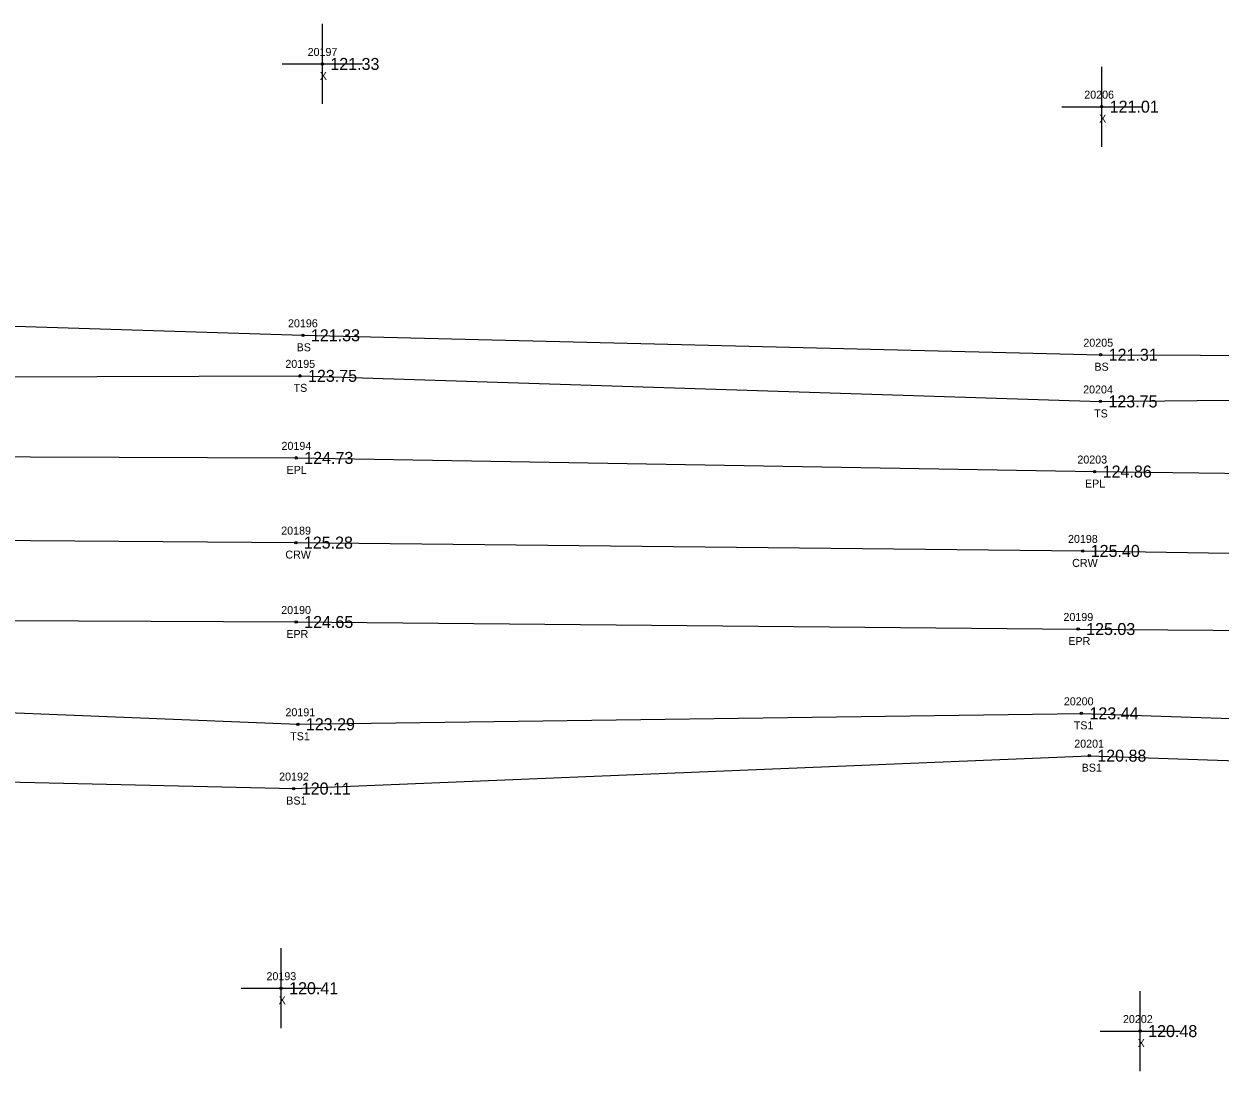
# Model space of a CAD drawing. Extents: x 2375812 to 2377225, y 1024470 to 1025135.
# Drawn here: x 2376931.3 to 2377080.8, y 1024855.9 to 1024986.7 of the extents above; entities that cross this region are included whole.
import ezdxf

# ---------------------------------------------------------------- set-up
doc = ezdxf.new("R2010")
doc.units = 0
for name, color, linetype in [('RD_DTM_BkLn1', 7, 'Continuous'), ('RD_DTM_BkLn2', 7, 'Continuous'), ('RD_DTM_BkLn_txCode', 7, 'Continuous'), ('RD_EX_Misc', 7, 'Continuous'), ('RD_EX_Misc_txCode', 7, 'Continuous'), ('RD_EX_Road', 7, 'Continuous'), ('RD_EX_Road_txCode', 7, 'Continuous'), ('RD_EX_TX_Misc_ELEV', 7, 'Continuous'), ('RD_EX_TX_Road_ELEV', 7, 'Continuous'), ('RD_HC_Survey_ELEV', 7, 'Continuous'), ('RD_HC_Survey_txCode', 7, 'Continuous'), ('RD_SMD_Locator', 7, 'Continuous')]:
    doc.layers.add(name, color=color, linetype=linetype)

msp = doc.modelspace()

# ---------------------------------------------------------------- linework, layer by layer
at = {"layer": 'RD_DTM_BkLn1'}
msp.add_lwpolyline([(2376561.75, 1024926.35), (2376659.86, 1024925.07), (2376762.41, 1024923.95), (2376865.76, 1024922.65), (2376965.3, 1024921.9), (2377063.64, 1024920.86), (2377113.34, 1024920.1), (2377166.94, 1024920.12), (2377217.3, 1024921.22)], dxfattribs=at)
at = {"layer": 'RD_DTM_BkLn2'}
for points in [[(2376538.09, 1024944), (2376550.49, 1024951.37), (2376563.43, 1024953.34), (2376659.84, 1024952.77), (2376765.68, 1024950.71), (2376864.8, 1024951), (2376966.18, 1024947.81), (2377065.88, 1024945.38), (2377115.79, 1024945.18), (2377168.04, 1024944.37), (2377216.91, 1024944.34)], [(2376561.81, 1024938.95), (2376565.65, 1024944.33), (2376658.56, 1024947.18), (2376764.14, 1024946.5), (2376864.38, 1024942.41), (2376965.82, 1024942.74), (2377065.85, 1024939.54), (2377114.14, 1024940.04), (2377167.94, 1024941.05), (2377217.02, 1024940.65)], [(2376561.53, 1024913.62), (2376561.38, 1024909.35), (2376658.21, 1024899.77), (2376672.96, 1024897.91), (2376688.03, 1024903.17), (2376760.99, 1024901.04), (2376828.16, 1024902.22), (2376853.81, 1024902.74), (2376860.1, 1024898.86), (2376865.34, 1024899.92), (2376875.73, 1024904.61), (2376896.78, 1024904.73), (2376899.24, 1024901.87), (2376965.55, 1024899.2), (2377063.48, 1024900.56), (2377114.6, 1024898.84), (2377167.13, 1024900.76), (2377217.62, 1024901.12)], [(2376543.21, 1024910.85), (2376558.6, 1024896.28), (2376588.49, 1024894.01), (2376656.25, 1024894.1), (2376679.22, 1024888.45), (2376688.36, 1024892.22), (2376760.25, 1024888.88), (2376862.95, 1024889.28), (2376867.73, 1024890.58), (2376879.38, 1024883.12), (2376893.75, 1024882.89), (2376900.24, 1024892.67), (2376965.04, 1024891.16), (2377064.46, 1024895.27), (2377115.01, 1024893.54), (2377167.33, 1024895.41), (2377217.32, 1024894.83)]]:
    msp.add_lwpolyline(points, dxfattribs=at)
at = {"layer": 'RD_EX_Misc'}
for p, q in [((2376968.61, 1024976.72), (2376968.61, 1024986.72)), ((2376963.61, 1024981.72), (2376973.61, 1024981.72)), ((2377066.01, 1024971.38), (2377066.01, 1024981.38)), ((2377061.01, 1024976.38), (2377071.01, 1024976.38)), ((2376963.46, 1024861.21), (2376963.46, 1024871.21)), ((2376958.46, 1024866.21), (2376968.46, 1024866.21)), ((2377070.82, 1024855.85), (2377070.82, 1024865.85)), ((2377065.82, 1024860.85), (2377075.82, 1024860.85))]:
    msp.add_line(p, q, dxfattribs=at)
at = {"layer": 'RD_EX_Road'}
for points in [[(2376561.85, 1024938.22), (2376659.62, 1024935.3), (2376763.51, 1024933.89), (2376865.73, 1024932.88), (2376965.35, 1024932.49), (2377065.13, 1024930.78), (2377114.03, 1024930.18), (2377167.22, 1024930.19), (2377217.07, 1024931.12)], [(2376561.38, 1024915.36), (2376658.71, 1024915.48), (2376761.9, 1024913.76), (2376865.54, 1024912.46), (2376965.34, 1024911.98), (2377063.07, 1024911.1), (2377113.55, 1024910.69), (2377167.38, 1024909.96), (2377217.4, 1024910.82)]]:
    msp.add_lwpolyline(points, dxfattribs=at)
at = {"layer": 'RD_SMD_Locator'}
for centre in [(2376968.61, 1024981.72), (2377066.01, 1024976.38), (2376966.18, 1024947.81), (2377065.88, 1024945.38), (2376965.82, 1024942.74), (2377065.85, 1024939.54), (2376965.35, 1024932.49), (2377065.13, 1024930.78), (2376965.3, 1024921.9), (2377063.64, 1024920.86), (2376965.34, 1024911.98), (2377063.07, 1024911.1), (2377063.48, 1024900.56), (2376965.55, 1024899.2), (2377064.46, 1024895.27), (2376965.04, 1024891.16), (2376963.46, 1024866.21), (2377070.82, 1024860.85)]:
    msp.add_circle(centre, 0.15, dxfattribs=at)

# ---------------------------------------------------------------- texts
at = {"layer": 'RD_DTM_BkLn_txCode'}
for s, p in [('20196', (2376964.32, 1024948.81)), ('20205', (2377063.72, 1024946.38)), ('BS', (2376965.4, 1024945.81)), ('20195', (2376963.99, 1024943.74)), ('BS', (2377065.1, 1024943.38)), ('TS', (2376965.02, 1024940.74)), ('20204', (2377063.69, 1024940.54)), ('TS', (2377065.06, 1024937.54)), ('20200', (2377061.28, 1024901.56)), ('20191', (2376964, 1024900.2)), ('TS1', (2377062.52, 1024898.56)), ('TS1', (2376964.59, 1024897.2)), ('20201', (2377062.58, 1024896.27)), ('20192', (2376963.21, 1024892.16)), ('BS1', (2377063.51, 1024893.27)), ('BS1', (2376964.1, 1024889.16))]:
    msp.add_text(s, height=1, dxfattribs=at).set_placement(p)
at = {"layer": 'RD_EX_Misc_txCode'}
for s, p in [('20197', (2376966.77, 1024982.72)), ('X', (2376968.29, 1024979.72)), ('20206', (2377063.83, 1024977.38)), ('X', (2377065.7, 1024974.38)), ('20193', (2376961.63, 1024867.21)), ('X', (2376963.15, 1024864.21)), ('20202', (2377068.67, 1024861.85)), ('X', (2377070.51, 1024858.85))]:
    msp.add_text(s, height=1, dxfattribs=at).set_placement(p)
at = {"layer": 'RD_EX_Road_txCode'}
for s, p in [('20194', (2376963.51, 1024933.49)), ('20203', (2377062.97, 1024931.78)), ('EPL', (2376964.14, 1024930.49)), ('EPL', (2377063.92, 1024928.78)), ('20190', (2376963.47, 1024912.98)), ('20199', (2377061.23, 1024912.1)), ('EPR', (2376964.11, 1024909.98)), ('EPR', (2377061.84, 1024909.1))]:
    msp.add_text(s, height=1, dxfattribs=at).set_placement(p)
at = {"layer": 'RD_EX_TX_Misc_ELEV'}
for s, p in [('121.33', (2376969.61, 1024980.97)), ('121.01', (2377067.01, 1024975.63)), ('121.33', (2376967.18, 1024947.06)), ('121.31', (2377066.88, 1024944.63)), ('123.75', (2376966.82, 1024941.99)), ('123.75', (2377066.85, 1024938.79)), ('123.44', (2377064.48, 1024899.81)), ('123.29', (2376966.55, 1024898.45)), ('120.88', (2377065.46, 1024894.52)), ('120.11', (2376966.04, 1024890.41)), ('120.41', (2376964.46, 1024865.46)), ('120.48', (2377071.82, 1024860.1))]:
    msp.add_text(s, height=1.5, dxfattribs=at).set_placement(p)
at = {"layer": 'RD_EX_TX_Road_ELEV'}
for s, p in [('124.73', (2376966.35, 1024931.74)), ('124.86', (2377066.13, 1024930.03)), ('124.65', (2376966.34, 1024911.23)), ('125.03', (2377064.07, 1024910.35))]:
    msp.add_text(s, height=1.5, dxfattribs=at).set_placement(p)
at = {"layer": 'RD_HC_Survey_ELEV'}
for s, p in [('125.28', (2376966.3, 1024921.15)), ('125.40', (2377064.64, 1024920.11))]:
    msp.add_text(s, height=1.5, dxfattribs=at).set_placement(p)
at = {"layer": 'RD_HC_Survey_txCode'}
for s, p in [('20189', (2376963.47, 1024922.9)), ('20198', (2377061.8, 1024921.86)), ('CRW', (2376963.99, 1024919.9)), ('CRW', (2377062.32, 1024918.86))]:
    msp.add_text(s, height=1, dxfattribs=at).set_placement(p)

doc.saveas('drawing.dxf')
